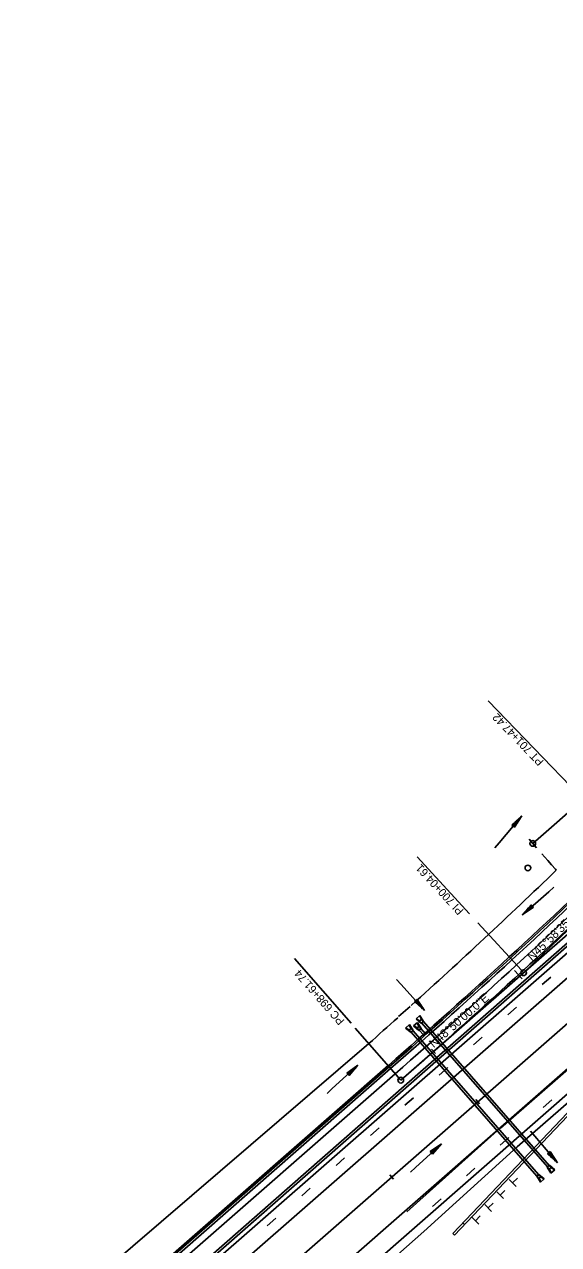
# Model space of a CAD drawing. Extents: x 1300404 to 1323571, y 234004 to 252077.
# Drawn here: x 1308709 to 1309176, y 239404 to 240472 of the extents above; entities that cross this region are included whole.
import ezdxf

# ---------------------------------------------------------------- set-up
doc = ezdxf.new("R2010")
doc.units = 0
for name, color, linetype in [('R_Barrel', 7, 'Continuous'), ('R_Barrier Wall', 7, 'Continuous'), ('R_Const Limits', 7, 'Continuous'), ('R_Draft', 7, 'Continuous'), ('R_FES', 7, 'Continuous'), ('R_Flow Arrows', 7, 'Continuous'), ('R_Horz Alg Annot', 7, 'Continuous'), ('R_Horz Alg Annot Leader', 7, 'Continuous'), ('R_Horz Alg Major Ticks', 7, 'Continuous'), ('R_Horz Alg Minor Ticks', 7, 'Continuous'), ('R_Horz Alg Tangents', 7, 'Continuous'), ('R_Horz Alg Tangents Text', 7, 'Continuous'), ('R_Lane Edge', 7, 'Continuous'), ('R_Pipe Culvert', 7, 'Continuous'), ('R_Proposed', 7, 'Continuous'), ('R_Shoulder', 7, 'Continuous'), ('R_Temp Barrier Wall', 7, 'Continuous'), ('R_Temp Travel Lane', 7, 'Continuous'), ('R_Temp Travel Stripe', 7, 'Continuous')]:
    doc.layers.add(name, color=color, linetype=linetype)

msp = doc.modelspace()

# ---------------------------------------------------------------- linework, layer by layer
at = {"layer": 'R_Barrel'}
for p, q in [((1309138.7, 239455.3), (1309132.6, 239461.3)), ((1309135.6, 239458.3), (1309139.9, 239462.6)), ((1309127.8, 239444.6), (1309121.7, 239450.6)), ((1309124.7, 239447.6), (1309128.9, 239451.8)), ((1309117.3, 239433.4), (1309111.2, 239439.5)), ((1309114.2, 239436.5), (1309118.5, 239440.7)), ((1309106.1, 239422.2), (1309100, 239428.3)), ((1309103.1, 239425.2), (1309107.3, 239429.5))]:
    msp.add_line(p, q, dxfattribs=at)
msp.add_circle((1309149, 239733.8), 2.5, dxfattribs=at)
at = {"layer": 'R_Barrier Wall'}
for p, q in [((1308711.5, 239285.2), (1309026.7, 239560.9)), ((1308712.3, 239284.2), (1309027.6, 239559.9))]:
    msp.add_line(p, q, dxfattribs=at)
for radius in [5712.7, 5714.1]:
    msp.add_arc((1305266.3, 243861.4), radius, 311.1667, 314.0235, dxfattribs=at)
at = {"layer": 'R_Const Limits'}
for p, q in [((1309035.8, 239603.8), (1309046, 239612.7)), ((1308689.6, 239305.6), (1309009.8, 239580.2))]:
    msp.add_line(p, q, dxfattribs=at)
msp.add_lwpolyline([(1309173.8, 239731.8), (1309173.1, 239732.7), (1309169.6, 239736.6), (1309166.5, 239740.2), (1309161.2, 239746.2)], dxfattribs=at)
for start, end in [(312.123, 313.8707), (311.62, 311.9623)]:
    msp.add_arc((1305232.5, 243831.7), 5687.1, start, end, dxfattribs=at)
at = {"layer": 'R_Draft'}
for p, q in [((1308397, 238971.9), (1312368.4, 242444.5)), ((1308407.8, 238959.5), (1312379.2, 242432.1)), ((1308447.3, 238914.3), (1312418.7, 242386.9)), ((1308458.2, 238901.9), (1312429.6, 242374.5)), ((1309037.8, 239548.2), (1312137.6, 242258.7))]:
    msp.add_line(p, q, dxfattribs=at)
at = {"layer": 'R_FES'}
for p, q in [((1309051.2, 239601.9), (1309054.6, 239604.8)), ((1309056, 239597.9), (1309051.2, 239601.9)), ((1309054, 239600.4), (1309051.2, 239601.9)), ((1309051.4, 239602), (1309054, 239600.4)), ((1309056, 239598.2), (1309051.4, 239602)), ((1309055.5, 239601.9), (1309054.4, 239604.7)), ((1309057.5, 239599.5), (1309054.4, 239604.7)), ((1309057.8, 239599.5), (1309054.6, 239604.8)), ((1309054.6, 239604.8), (1309055.5, 239601.9)), ((1309056, 239598.2), (1309057.5, 239599.5)), ((1309057.8, 239599.5), (1309056, 239597.9)), ((1309057.5, 239599.5), (1309057.8, 239599.5)), ((1309042, 239593.8), (1309045.4, 239596.8)), ((1309046.9, 239589.9), (1309042, 239593.8)), ((1309044.9, 239592.3), (1309042, 239593.8)), ((1309042.2, 239594), (1309044.9, 239592.3)), ((1309046.9, 239590.2), (1309042.2, 239594)), ((1309046.4, 239593.9), (1309045.2, 239596.6)), ((1309048.4, 239591.6), (1309045.2, 239596.6)), ((1309048.7, 239591.6), (1309045.4, 239596.8)), ((1309045.4, 239596.8), (1309046.4, 239593.9)), ((1309046.9, 239590.2), (1309048.4, 239591.6)), ((1309048.7, 239591.6), (1309046.9, 239589.9)), ((1309046.9, 239590.2), (1309046.9, 239589.9)), ((1309048.4, 239591.6), (1309048.7, 239591.6)), ((1309048.9, 239595.7), (1309052.3, 239598.7)), ((1309053.7, 239591.8), (1309048.9, 239595.7)), ((1309051.7, 239594.3), (1309048.9, 239595.7)), ((1309049.1, 239595.9), (1309051.7, 239594.3)), ((1309053.7, 239592.1), (1309049.1, 239595.9)), ((1309053.2, 239595.8), (1309052.1, 239598.5)), ((1309055.3, 239593.5), (1309052.1, 239598.5)), ((1309055.6, 239593.5), (1309052.3, 239598.7)), ((1309052.3, 239598.7), (1309053.2, 239595.8)), ((1309053.7, 239592.1), (1309055.3, 239593.5)), ((1309055.6, 239593.5), (1309053.7, 239591.8)), ((1309053.7, 239592.1), (1309053.7, 239591.8)), ((1309055.3, 239593.5), (1309055.6, 239593.5)), ((1309056, 239598.2), (1309056, 239597.9)), ((1309165.9, 239472.2), (1309167.8, 239473.9)), ((1309165.9, 239472.2), (1309169.2, 239467)), ((1309166.2, 239472.2), (1309165.9, 239472.2)), ((1309167.7, 239473.6), (1309166.2, 239472.2)), ((1309166.2, 239472.2), (1309169.4, 239467.1)), ((1309167.7, 239473.6), (1309167.8, 239473.9)), ((1309167.7, 239473.6), (1309172.4, 239469.8)), ((1309167.8, 239473.9), (1309172.6, 239469.9)), ((1309169.7, 239471.4), (1309172.6, 239469.9)), ((1309172.4, 239469.8), (1309169.7, 239471.4)), ((1309156.7, 239464.2), (1309158.6, 239465.8)), ((1309156.7, 239464.2), (1309160, 239458.9)), ((1309157, 239464.2), (1309156.7, 239464.2)), ((1309158.6, 239465.5), (1309157, 239464.2)), ((1309157, 239464.2), (1309160.2, 239459.1)), ((1309158.6, 239465.8), (1309163.4, 239461.9)), ((1309158.6, 239465.5), (1309158.6, 239465.8)), ((1309158.6, 239465.5), (1309163.2, 239461.7)), ((1309159.1, 239461.9), (1309160.2, 239459.1)), ((1309160, 239458.9), (1309159.1, 239461.9)), ((1309163.4, 239461.9), (1309160, 239458.9)), ((1309160.6, 239463.4), (1309163.4, 239461.9)), ((1309163.2, 239461.7), (1309160.6, 239463.4)), ((1309168.2, 239469.9), (1309169.4, 239467.1)), ((1309169.2, 239467), (1309168.2, 239469.9)), ((1309172.6, 239469.9), (1309169.2, 239467))]:
    msp.add_line(p, q, dxfattribs=at)
for centre, major_axis in [((1309054.4, 239601.4), (-0.787, 0.862)), ((1309045.3, 239593.4), (-0.803, 0.846)), ((1309052.2, 239595.3), (-0.793, 0.856)), ((1309169.3, 239470.3), (0.793, -0.856)), ((1309160.2, 239462.3), (0.793, -0.856))]:
    msp.add_ellipse(centre, major_axis=major_axis, ratio=0.999949, start_param=2.010439, end_param=4.34099, dxfattribs=at)
at = {"layer": 'R_Flow Arrows'}
for p, q in [((1309135, 239771.3), (1309143.7, 239779.3)), ((1309135, 239771.3), (1309137.3, 239769.4)), ((1309137.3, 239769.4), (1309143.7, 239779.3)), ((1309152, 239701.7), (1309144.1, 239692.9)), ((1309154, 239699.4), (1309144.1, 239692.9)), ((1309154, 239699.4), (1309152, 239701.7)), ((1309052, 239618.9), (1309049.7, 239616.9)), ((1309049.7, 239616.9), (1309058.7, 239609.2)), ((1309052, 239618.9), (1309058.7, 239609.2)), ((1308990.6, 239554.4), (1309000.3, 239561.2)), ((1308992.6, 239552.2), (1309000.3, 239561.2)), ((1308990.6, 239554.4), (1308992.6, 239552.2)), ((1309063.6, 239485.8), (1309073.3, 239492.6)), ((1309065.7, 239483.6), (1309073.3, 239492.6)), ((1309063.6, 239485.8), (1309065.7, 239483.6)), ((1309168.5, 239485.8), (1309166.2, 239483.8)), ((1309166.2, 239483.8), (1309175, 239475.9)), ((1309168.5, 239485.8), (1309175, 239475.9))]:
    msp.add_line(p, q, dxfattribs=at)
for points in [[(1309120.2, 239751.4), (1309123.9, 239755.8), (1309143.7, 239779.3)], [(1309135.2, 239771.1), (1309136.7, 239772.9)], [(1309135.5, 239770.9), (1309138.5, 239774.5)], [(1309135.7, 239770.7), (1309139.7, 239775.5), (1309140.2, 239776.1)], [(1309135.9, 239770.5), (1309139.9, 239775.3), (1309142, 239777.7)], [(1309136.4, 239770.1), (1309140.4, 239774.9), (1309142.4, 239777.3)], [(1309136.6, 239769.9), (1309140.6, 239774.7), (1309141.2, 239775.3)], [(1309136.9, 239769.7), (1309139.9, 239773.3)], [(1309137.1, 239769.6), (1309138.6, 239771.4)], [(1309171.6, 239716.9), (1309167.3, 239713), (1309144.2, 239692.8)], [(1309152.8, 239700.8), (1309148.1, 239696.7), (1309145.7, 239694.6)], [(1309153.2, 239700.3), (1309148.5, 239696.2), (1309146.1, 239694.2)], [(1309152.6, 239701), (1309147.9, 239696.9), (1309147.2, 239696.4)], [(1309153.4, 239700.1), (1309148.7, 239696), (1309148, 239695.5)], [(1309152.4, 239701.2), (1309148.8, 239698.2)], [(1309153.6, 239699.8), (1309150, 239696.8)], [(1309152.2, 239701.5), (1309150.4, 239699.9)], [(1309153.8, 239699.6), (1309152, 239698.1)], [(1309034.2, 239636.2), (1309038.1, 239631.9), (1309058.7, 239609.2)], [(1309049.9, 239617.1), (1309051.5, 239615.3)], [(1309050.2, 239617.3), (1309053.3, 239613.8)], [(1309050.4, 239617.5), (1309054.6, 239612.9), (1309055.1, 239612.3)], [(1309050.6, 239617.7), (1309054.8, 239613.1), (1309056.9, 239610.7)], [(1309051.1, 239618.1), (1309055.3, 239613.5), (1309057.4, 239611.1)], [(1309051.3, 239618.3), (1309055.5, 239613.7), (1309056, 239613.1)], [(1309051.5, 239618.5), (1309054.7, 239615)], [(1309051.7, 239618.7), (1309053.3, 239617)], [(1308973.4, 239536.6), (1308977.6, 239540.5), (1309000.3, 239561.2)], [(1308991, 239554), (1308994.4, 239557.1)], [(1308991.2, 239553.7), (1308995.8, 239557.9), (1308996.4, 239558.5)], [(1308991.4, 239553.5), (1308996, 239557.7), (1308998.3, 239559.9)], [(1308991.8, 239553.1), (1308996.4, 239557.3), (1308998.7, 239559.4)], [(1308992, 239552.8), (1308996.6, 239557.1), (1308997.2, 239557.6)], [(1308990.8, 239554.2), (1308992.5, 239555.8)], [(1308992.2, 239552.6), (1308995.7, 239555.8)], [(1308992.4, 239552.4), (1308994.2, 239554)], [(1309151.2, 239503.5), (1309155, 239499.1), (1309175, 239475.9)], [(1309046.4, 239467.9), (1309050.7, 239471.8), (1309073.3, 239492.6)], [(1309063.8, 239485.6), (1309065.6, 239487.2)], [(1309064, 239485.4), (1309067.5, 239488.5)], [(1309064.2, 239485.1), (1309068.8, 239489.3), (1309069.4, 239489.9)], [(1309064.4, 239484.9), (1309069, 239489.1), (1309071.4, 239491.3)], [(1309064.9, 239484.5), (1309069.4, 239488.7), (1309071.8, 239490.8)], [(1309065.1, 239484.2), (1309069.6, 239488.4), (1309070.3, 239489)], [(1309065.3, 239484), (1309068.7, 239487.2)], [(1309065.5, 239483.8), (1309067.2, 239485.4)], [(1309166.4, 239484), (1309168, 239482.2)], [(1309166.7, 239484.2), (1309169.7, 239480.6)], [(1309166.9, 239484.4), (1309171, 239479.7), (1309171.5, 239479)], [(1309167.1, 239484.6), (1309171.2, 239479.9), (1309173.3, 239477.5)], [(1309167.6, 239485), (1309171.7, 239480.3), (1309173.7, 239477.9)], [(1309167.8, 239485.2), (1309171.9, 239480.5), (1309172.4, 239479.8)], [(1309168.1, 239485.4), (1309171.1, 239481.8)], [(1309168.3, 239485.6), (1309169.8, 239483.8)]]:
    msp.add_lwpolyline(points, dxfattribs=at)
at = {"layer": 'R_Horz Alg Annot Leader'}
for points in [[(1309194.3, 239797.2), (1309114.2, 239880.1)], [(1309194.3, 239797.2), (1309114.2, 239880.1)], [(1309052.2, 239743.5), (1309097.9, 239693.8)], [(1309052.2, 239743.5), (1309097.9, 239693.8)], [(1309105.3, 239685.8), (1309143.4, 239644.3)], [(1309105.3, 239685.8), (1309143.4, 239644.3)], [(1308994.3, 239598), (1308944.8, 239654.5)], [(1308994.3, 239598), (1308944.8, 239654.5)], [(1309144.7, 239643), (1309145.3, 239642.2)], [(1309144.7, 239643), (1309145.3, 239642.2)], [(1309037.8, 239548.2), (1308998, 239593.6)], [(1309037.8, 239548.2), (1308998, 239593.6)]]:
    msp.add_lwpolyline(points, dxfattribs=at)
at = {"layer": 'R_Horz Alg Major Ticks'}
for points in [[(1309150, 239759), (1309156.6, 239751.5)], [(1309150, 239759), (1309156.6, 239751.5)], [(1309150, 239759), (1309156.6, 239751.5)], [(1309150, 239759), (1309156.6, 239751.5)], [(1309137.4, 239644.1), (1309144.1, 239636.8)], [(1309137.4, 239644.1), (1309144.1, 239636.8)]]:
    msp.add_lwpolyline(points, dxfattribs=at)
at = {"layer": 'R_Horz Alg Minor Ticks'}
for points in [[(1309151.7, 239757.1), (1309155, 239753.4)], [(1309151.7, 239757.1), (1309155, 239753.4)], [(1309064.8, 239575.3), (1309068.2, 239571.6)], [(1309064.8, 239575.3), (1309068.2, 239571.6)], [(1309103.4, 239531.2), (1309106.7, 239527.5)], [(1309103.4, 239531.2), (1309106.7, 239527.5)], [(1309028.2, 239465.4), (1309031.5, 239461.6)], [(1309028.2, 239465.4), (1309031.5, 239461.6)]]:
    msp.add_lwpolyline(points, dxfattribs=at)
at = {"layer": 'R_Horz Alg Tangents'}
for p, q in [((1309145.3, 239642.2), (1309248.1, 239741.5)), ((1309145.3, 239642.2), (1309248.1, 239741.5)), ((1309037.8, 239548.2), (1309145.3, 239642.2)), ((1309037.8, 239548.2), (1309145.3, 239642.2))]:
    msp.add_line(p, q, dxfattribs=at)
at = {"layer": 'R_Lane Edge'}
msp.add_line((1308717.7, 239278.3), (1309032.8, 239553.8), dxfattribs=at)
msp.add_arc((1305266.3, 243861.4), 5722.1, 311.1667, 314.0235, dxfattribs=at)
at = {"layer": 'R_Pipe Culvert'}
for p, q in [((1309057.7, 239599.4), (1309167.6, 239473.7)), ((1309156.9, 239464.3), (1309047, 239590.1)), ((1309158.4, 239465.7), (1309048.5, 239591.4)), ((1309057.9, 239587.5), (1309053.9, 239592)), ((1309059.4, 239588.8), (1309055.4, 239593.3)), ((1309056.1, 239598.1), (1309166.1, 239472.4)), ((1309057.9, 239587.5), (1309059.4, 239588.8))]:
    msp.add_line(p, q, dxfattribs=at)
at = {"layer": 'R_Proposed'}
for p, q in [((1308427.6, 238936.9), (1312793.8, 242754.8)), ((1308427.6, 238936.9), (1312793.8, 242754.8)), ((1309153.3, 239755.3), (1309454.5, 240018.5)), ((1309153.3, 239755.3), (1309454.5, 240018.5))]:
    msp.add_line(p, q, dxfattribs=at)
for centre in [(1309153.3, 239755.3), (1309153.3, 239755.3), (1309145.3, 239642.2), (1309145.3, 239642.2), (1309037.8, 239548.2), (1309037.8, 239548.2)]:
    msp.add_circle(centre, 2.5, dxfattribs=at)
msp.add_arc((1305266.3, 243861.4), 5729.6, 311.16667, 314.02346, dxfattribs=at)
msp.add_arc((1305266.3, 243861.4), 5729.6, 311.16667, 314.02346, dxfattribs=at)
at = {"layer": 'R_Shoulder'}
msp.add_line((1308713.7, 239282.7), (1309028.9, 239558.4), dxfattribs=at)
msp.add_arc((1305266.3, 243861.4), 5716.1, 311.1667, 314.0235, dxfattribs=at)
at = {"layer": 'R_Temp Barrier Wall'}
for p, q in [((1309216.1, 239554), (1309083.3, 239414.1)), ((1309217.6, 239552.7), (1309084.7, 239412.7)), ((1309093.6, 239422.1), (1309092.2, 239423.5)), ((1309084.7, 239412.7), (1309083.3, 239414.1))]:
    msp.add_line(p, q, dxfattribs=at)
for points in [[(1311027.3, 241280.9), (1310559.7, 240872.1), (1309471.9, 239921.2), (1308468.9, 239041.6)], [(1311028.6, 241279.4), (1310561.1, 240870.6), (1309473.3, 239919.7), (1308470.2, 239040.1)]]:
    msp.add_lwpolyline(points, dxfattribs=at)
at = {"layer": 'R_Temp Travel Lane'}
for p, q in [((1309139.5, 239489.8), (1310268.9, 240477.2)), ((1309125.1, 239506.4), (1309953.3, 240230.4)), ((1309125.1, 239506.3), (1309935.8, 240215.2)), ((1309139.6, 239489.8), (1309215.3, 239556)), ((1309125.1, 239506.4), (1309043.1, 239433.2)), ((1309139.6, 239489.8), (1309058.1, 239415.9))]:
    msp.add_line(p, q, dxfattribs=at)
at = {"layer": 'R_Temp Travel Stripe'}
for p, q in [((1309169.1, 239638.4), (1309161.6, 239631.8)), ((1309139.1, 239612), (1309131.5, 239605.4)), ((1309109, 239585.7), (1309101.5, 239579.1)), ((1309078.9, 239559.3), (1309071.4, 239552.7)), ((1309048.8, 239532.9), (1309041.3, 239526.3)), ((1309162.4, 239524.4), (1309169.9, 239531)), ((1309018.8, 239506.5), (1309011.2, 239499.9)), ((1309132.3, 239498.1), (1309124.9, 239491.3)), ((1308988.7, 239480.2), (1308981.2, 239473.6)), ((1309102.7, 239471.2), (1309095.3, 239464.5)), ((1308958.6, 239453.8), (1308951.1, 239447.2)), ((1309073, 239444.3), (1309065.6, 239437.6)), ((1308928.5, 239427.4), (1308921, 239420.8)), ((1309013.4, 239376.7), (1309058.1, 239415.9))]:
    msp.add_line(p, q, dxfattribs=at)

# ---------------------------------------------------------------- texts
at = {"layer": 'R_Horz Alg Annot'}
for s, rotation, p in [('PT 701+47.42', 134.0235, (1309163.4, 239827.3)), ('PT 701+47.42', 134.0235, (1309163.4, 239827.3)), ('PI 700+04.61', 132.5951, (1309093.3, 239696.7)), ('PI 700+04.61', 132.5951, (1309093.3, 239696.7)), ('PC 698+61.74', 131.1667, (1308989, 239600.3)), ('PC 698+61.74', 131.1667, (1308989, 239600.3))]:
    msp.add_text(s, height=7, rotation=rotation, dxfattribs=at).set_placement(p)
at = {"layer": 'R_Horz Alg Tangents Text'}
for s, rotation, p in [('N45%%d58\'35.5"E', 44.0235, (1309152.7, 239652)), ('N48%%d50\'00.0"E', 41.1667, (1309066.6, 239576.1))]:
    msp.add_text(s, height=7.5, rotation=rotation, dxfattribs=at).set_placement(p)

doc.saveas('drawing.dxf')
